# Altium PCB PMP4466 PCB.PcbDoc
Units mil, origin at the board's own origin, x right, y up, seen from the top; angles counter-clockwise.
Board outline 1720 x 1390 mil, 2 copper layers (Top Layer, Bottom Layer), stack 62 mil thick; 65 components, 38 nets, 155 pads, 8 vias.
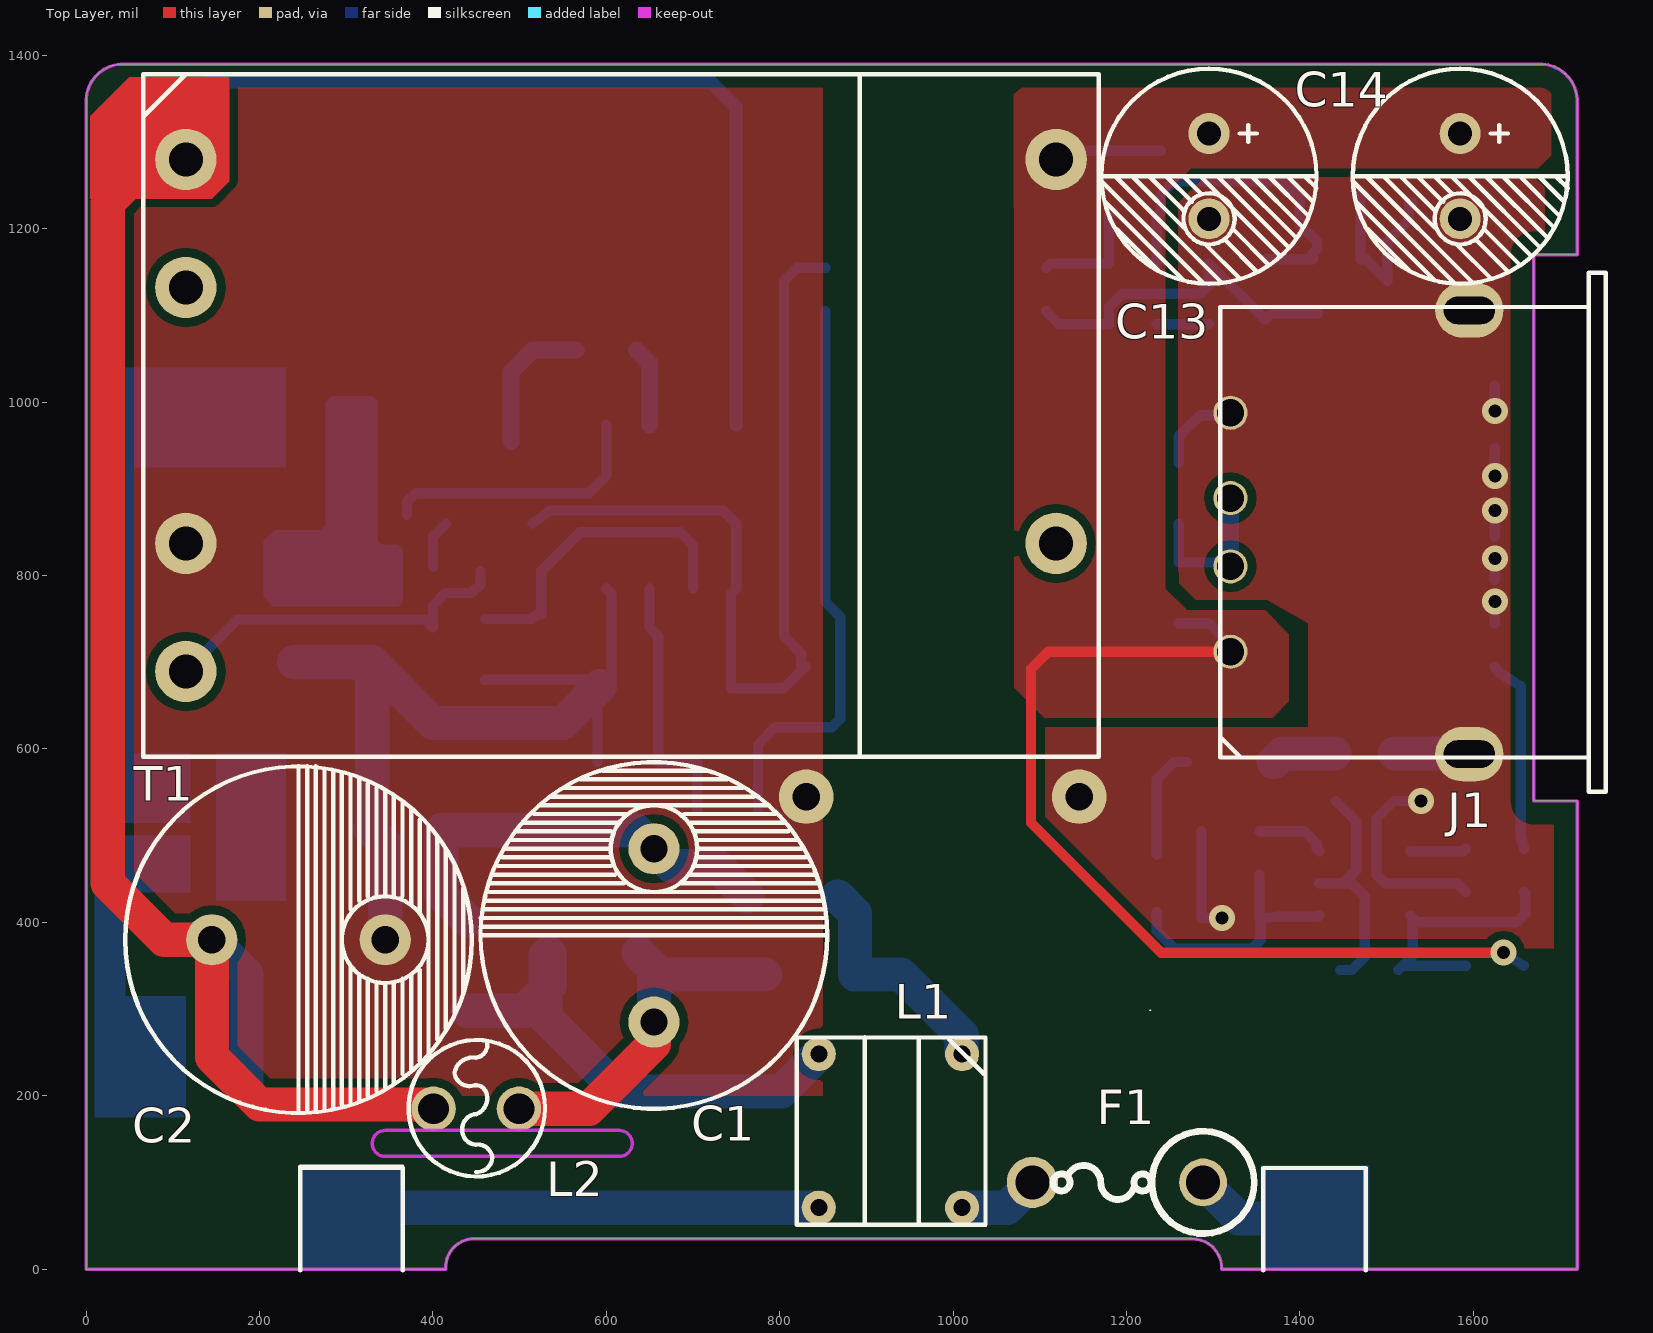
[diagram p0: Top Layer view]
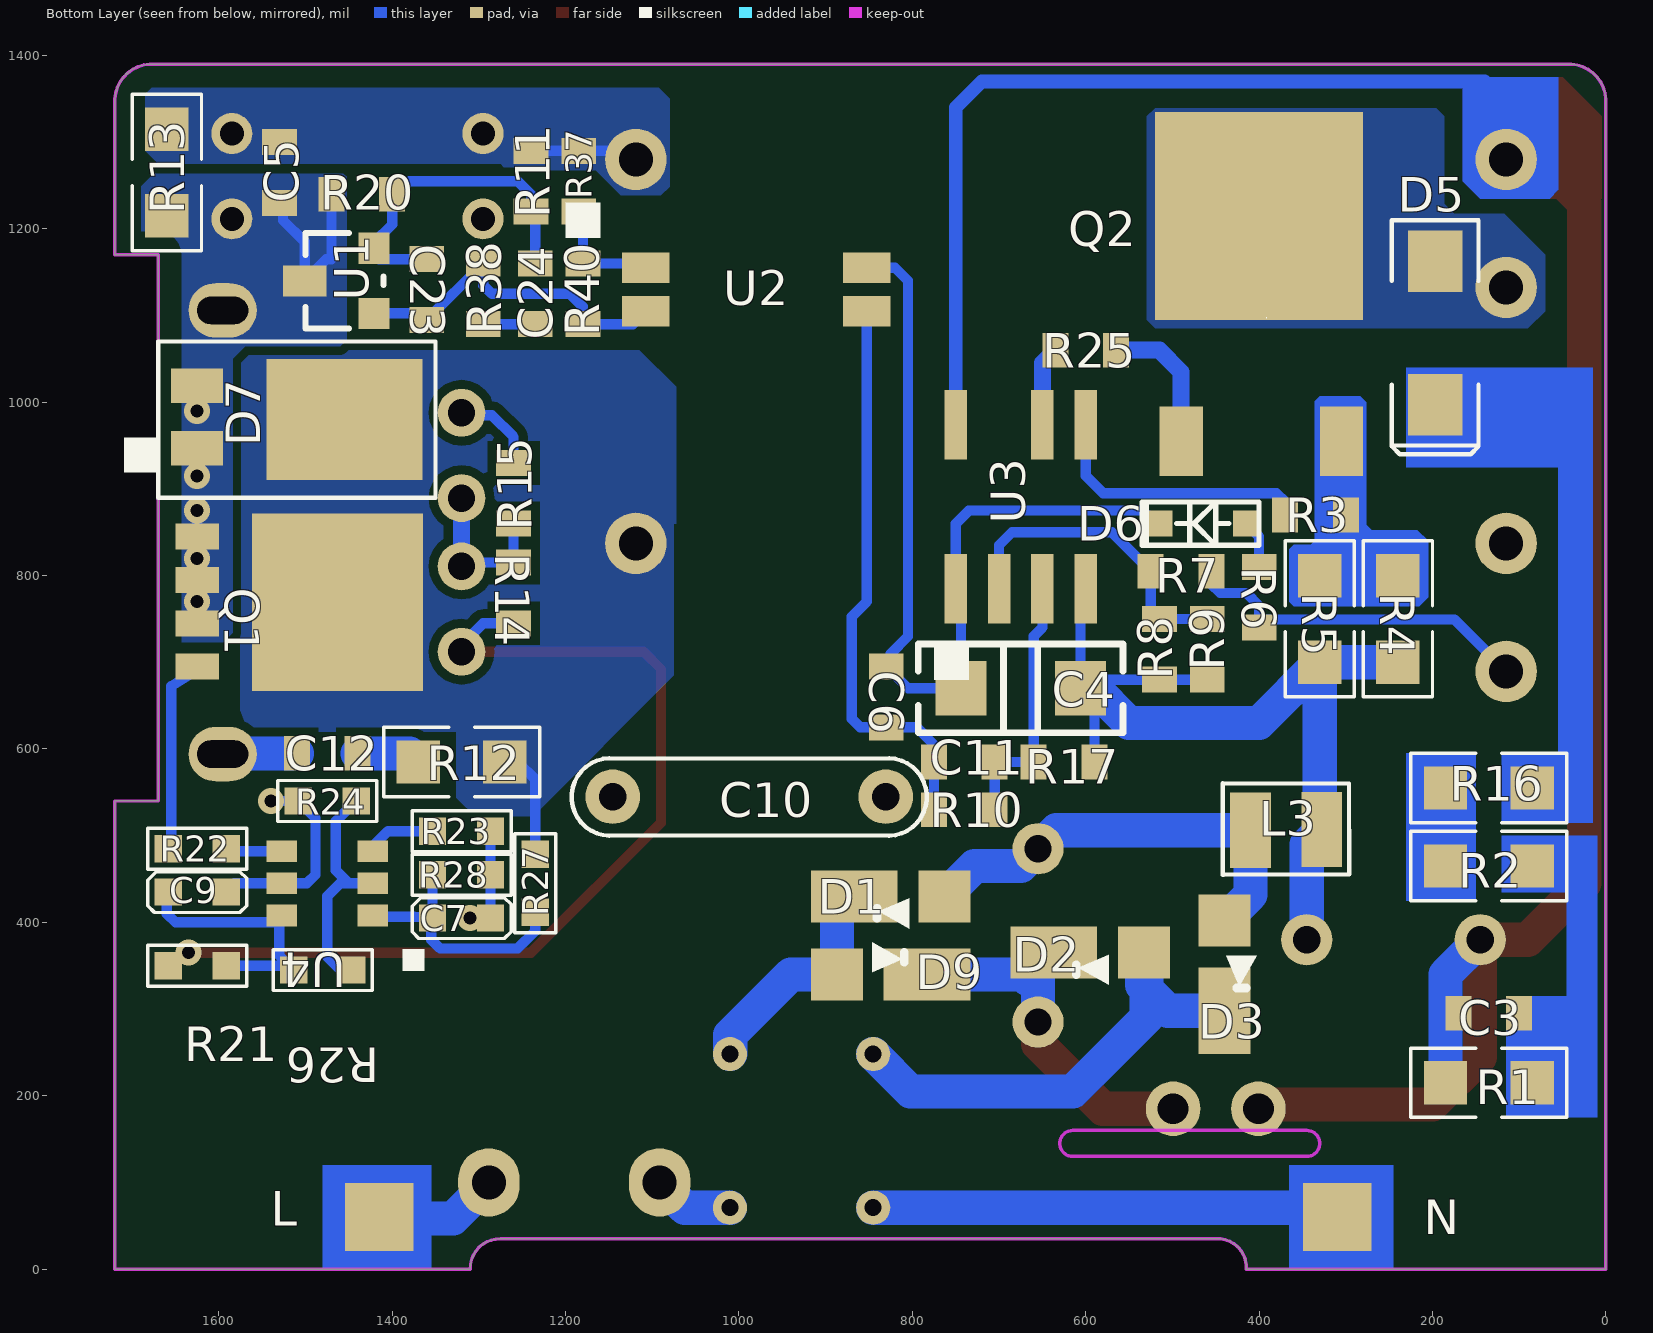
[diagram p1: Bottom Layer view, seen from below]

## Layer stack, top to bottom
Top Solder: solder mask 0.4, Solder Resist, Dk 3.5
Top Layer: signal copper 1.4
Dielectric1: core 59.2, FR-4, Dk 4.8
Bottom Layer: signal copper 1.4
Bottom Solder: solder mask 0.4, Solder Resist, Dk 3.5

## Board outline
0,0 0,1350 0,1349.95 cw(c42.5,1347.5) 39.98,1390 40,1390 1680,1390 1679.95,1390 cw(c1677.5,1347.5) 1720,1350.02 1720,1350 1720,1170 1670,1170 1670,540 1720,540 1720,0 1310,0 ccw(c1275.83,0.83) 1275,35 450,35 ccw(c447.5,2.5) 415,0

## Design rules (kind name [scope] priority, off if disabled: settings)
AcuteAngle [All] p1: minimum=4.50000000000000E+0001 checktracksonly=FALSE
AssemblyTestPointUsage [All] p1: valid=2
Clearance Clearance_BoardEdge_MountingHoles [OnCopper and InComponentClass('Mounting Holes') vs IsKeepOut] p1: gap=40
Clearance Clearance_BoardEdge_Poly [OnCopper and InPoly vs IsKeepOut] p2: gap=25
Clearance Clearance_BoardEdge [OnCopper and Not InComponentClass('Logo') and not InComponentClass('FiducialMark') and not InRegion(1000,500,4000,800) and Not IsKeepout vs IsKeepOut] p3: gap=5
Clearance Clearance_Poly [InPolygon] p4: gap=6
Clearance [All] p5: gap=6
ComponentClearance ComponentClearance_Logo [All] p1: gap=10 collisioncheckmode=3 verticalgap=10 showdistances=TRUE
ComponentClearance ComponentClearance_ScrewToNut [(HasFootprint('NY PMS 440 0025 PH')) vs (HasFootprint('Keystone_1902C'))] p2: gap=5 collisioncheckmode=3 verticalgap=10 showdistances=FALSE
ComponentClearance ComponentClearance_MountingHoles [InComponentClass('Mounting Holes')] p3: gap=10 collisioncheckmode=3 verticalgap=100000 showdistances=FALSE
ComponentClearance ComponentClearance_SmallPassives [HasFootprint('0201*') or HasFootprint('0402*') or HasFootprint('0508') or HasFootprint('0603*') or HasFootprint('0612') or HasFootprint('0805*') or HasFootprint('0815*') or HasFootprint('0830*') or HasFootprint('1206*') or HasFootprint('1210*') or HasFootprint('1808*') or HasFootprint('1812*') or HasFootprint('1825*') or HasFootprint('2010*') or HasFootprint('2220*') or HasFootprint('2225*') or HasFootprint('2512*') or HasFootprint('2728*') or HasFootprint('3518*') vs HasFootprint('0201*') or HasFootprint('0402*') or HasFootprint('0508') or HasFootprint('0603*') or HasFootprint('0612') or HasFootprint('0805*') or HasFootprint('0815*') or HasFootprint('0830*') or HasFootprint('1206*') or HasFootprint('1210*') or HasFootprint('1808*') or HasFootprint('1812*') or HasFootprint('1825*') or HasFootprint('2010*') or HasFootprint('2220*') or HasFootprint('2225*') or HasFootprint('2512*') or HasFootprint('2728*') or HasFootprint('3518*')] p4: gap=10 collisioncheckmode=3 verticalgap=10 showdistances=FALSE
ComponentClearance ComponentClearance_THtoSMT [IsThruComponent vs IsSMTComponent] p5: gap=10 collisioncheckmode=3 verticalgap=100000 showdistances=FALSE
ComponentClearance ComponentClearance_THtoTH [IsThruComponent vs IsThruComponent] p6: gap=10 collisioncheckmode=3 verticalgap=100000 showdistances=FALSE
ComponentClearance [All] p7: gap=10 collisioncheckmode=3 verticalgap=10 showdistances=FALSE
DiffPairsRouting [All] p1: maxlimit=100 minlimit=10 mostfreqgap=10 toplayer_minwidth=15 toplayer_maxwidth=15 toplayer_prefwidth=15 bottomlayer_minwidth=15 bottomlayer_maxwidth=15 bottomlayer_prefwidth=15 maxuncoupledlength=1000
FabricationTestPointUsage TestPointUsage [All] p1: valid=2 allowmultiple=FALSE
FabricationTestpoint Testpoint [All] p1: side=3 testpointundercomponent=TRUE minsize=40 maxsize=100 preferedsize=60 minholesize=0 maxholesize=40 preferedholesize=32 testpointgrid=1 allowsidetop=TRUE allowsidebottom=TRUE usegrid=TRUE gridtolerance=0.01
FanoutControl Fanout_LCC [IsLCC] p1: bgadir=Out bgaviamode=Centered fanoutstyle=Auto fanoutdirection=Alternating viagrid=1 // Fanout_LCC (Default Rule)
FanoutControl Fanout_BGA [IsBGA] p2: bgadir=Out bgaviamode=Centered fanoutstyle=Auto fanoutdirection=Alternating viagrid=1 // Fanout_BGA (Default Rule)
FanoutControl Fanout_Default [All] p4: bgadir=Out bgaviamode=Centered fanoutstyle=Auto fanoutdirection=Alternating viagrid=1 // Fanout_Default (Default Rule)
FanoutControl Fanout_Small [(CompPinCount < 5)] p5: bgadir=Out bgaviamode=Centered fanoutstyle=Auto fanoutdirection=OutThenIn viagrid=1 // Fanout_Small (Default Rule)
HoleSize [All] p1: absolutevalues=TRUE maxlimit=251 minlimit=6 maxpercent=80.000 minpercent=20.000
MinimumAnnularRing [All] p1: minimumring=3
MinimumSolderMaskSliver MinimumSolderMaskSliver_Logo [InComponentClass('Logo') vs InComponentClass('Logo')] p1: minsoldermaskwidth=0.7
MinimumSolderMaskSliver [All] p2: minsoldermaskwidth=0
PlaneConnect [All] p1: planeconnectstyle=Direct reliefexpansion=10 reliefentries=4 reliefconductorwidth=10 reliefairgap=10
PolygonConnect [All] p1: connectstyle=Direct reliefconductorwidth=10 reliefentries=4 polygonreliefangle="90 Angle" airgapwidth=10
RoutingCorners [All] p1: cornerstyle=45-Degree minsetback=10 maxsetback=100
RoutingVias [All] p1: holewidth=16 width=34 viastyle="Through Hole" minholewidth=8 minwidth=16 maxholewidth=40 maxwidth=65
SMDToCorner [All] p1: distance=0
SilkToSilkClearance [All] p1: silktosilkclearance=0
SilkToSolderMaskClearance SilkscreenOverComponentPads [IsPad] p1: minsilkscreentomaskgap=0 clearancetoexposedcopper=TRUE
SolderMaskExpansion [All] p1: expansion=3
UnpouredPolygon [All] p1: allowunpoured=FALSE
Width [All] p1: maxlimit=100 minlimit=6 preferedwidth=10 checkconnectedcopper=TRUE
14 further rules are at their usual default settings.

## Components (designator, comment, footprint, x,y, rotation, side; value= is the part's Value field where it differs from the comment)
C1 "ECAP$5C$200$5C$400A" ECAP$5C$200$5C$400A 655,285 r90 top
C2 "ECAP$5C$200$5C$400A" ECAP$5C$200$5C$400A 145,380 r0 top
C3 "C603" C603 135,295 r0 bottom
C4 "C1206" C1206 675,670 r0 bottom
C5 "C603" C603 1530,1265 r90 bottom
C6 "C603" C603 830,660 r90 bottom
C7 "0603C(W)$2F$3" 0603C(W)$2F$3 1320,405 r0 bottom
C9 "0603C(W)$2F$3" 0603C(W)$2F$3 1625,435 r0 bottom
C10 "Y-CAP" Y-CAP 1185,545 r180 bottom
C11 "C603" C603 740,585 r180 bottom
C12 "C603" C603 1475,595 r180 bottom
C13 "ECAP$5C$2.5$5C$6.3" ECAP$5C$2.5$5C$6.3 1295.28,1309.96 r270 top
C14 "ECAP$5C$2.5$5C$6.3" ECAP$5C$2.5$5C$6.3 1585,1309.96 r270 top
C23 "C603" C603 1360,1130 r270 bottom
C24 "C603" C603 1235,1125 r270 bottom
D1 "POWERDI_123" POWERDI_123 825,430 r180 bottom
D2 "POWERDI_123" POWERDI_123 595,365 r180 bottom
D3 "POWERDI_123" POWERDI_123 440,340 r90 bottom
D5 "SMA" SMA 196.85,1080 r270 bottom
D6 "SOD323" SOD323 465,860 r0 bottom
D7 "POWER_DI" POWER_DI 1555,980 r270 bottom
D9 "POWERDI_123" POWERDI_123 825,340 r0 bottom
F1 "F-7.2X2.7-P5" F-7.2X2.7-P5 1190,100 r180 top
J1 "USB-BYDAAAAAA" USB-BYDAAAAAA 1320,850 r90 top
L "H1.0" H1.0 1415,60 r180 bottom
L1 "CMNEE8.3AA" CMNEE8.3AA 855,125 r0 top
L2 "L_0406A" L_0406A 450,185 r180 top
L3 "L-0805$2F$3" L-0805$2F$3 375,510 r180 bottom
N "H1.0" H1.0 310,60 r180 bottom
Q1 "QFN5X6MM" QFN5X6MM 1510,770 r270 bottom
Q2 "KTP" KTP 400,1125 r180 bottom
R1 "CAP$5C$0805$5C$B" CAP$5C$0805$5C$B 135,215 r180 bottom
R2 "CAP$5C$0805$5C$B" CAP$5C$0805$5C$B 135,465 r0 bottom
R3 "R603" R603 335,870 r0 bottom
R4 "CAP$5C$0805$5C$B" CAP$5C$0805$5C$B 240,750 r270 bottom
R5 "CAP$5C$0805$5C$B" CAP$5C$0805$5C$B 330,750 r270 bottom
R6 "R603" R603 400,775 r90 bottom
R7 "R603" R603 490,805 r0 bottom
R8 "R603" R603 515,715 r90 bottom
R9 "R603" R603 460,715 r90 bottom
R10 "R603" R603 740,530 r180 bottom
R11 "R603" R603 1240,1255 r270 bottom
R12 "CAP$5C$0805$5C$B" CAP$5C$0805$5C$B 1320,585 r0 bottom
R13 "CAP$5C$0805$5C$B" CAP$5C$0805$5C$B 1660,1265 r90 bottom
R14 "R603" R603 1260,780 r270 bottom
R15 "R603" R603 1260,895 r270 bottom
R16 "CAP$5C$0805$5C$B" CAP$5C$0805$5C$B 135,555 r180 bottom
R17 "R603" R603 625,585 r0 bottom
R20 "R603" R603 1435,1240 r0 bottom
R21 "0603(W)" 0603(W) 1625,350 r0 bottom
R22 "0603(W)" 0603(W) 1625,485 r0 bottom
R23 "0603(W)" 0603(W) 1320,505 r0 bottom
R24 "0603(W)" 0603(W) 1475,540 r180 bottom
R25 "R603" R603 600,1060 r0 bottom
R26 "0603(W)" 0603(W) 1480,345 r0 bottom
R27 "0603(W)" 0603(W) 1235,445 r90 bottom
R28 "0603(W)" 0603(W) 1320,455 r0 bottom
R37 "R603" R603 1185,1255 r270 bottom
R38 "R603" R603 1295,1125 r90 bottom
R40 "R603" R603 1180,1125 r270 bottom
T1 "EFD20-2AAA" EFD20-2AAA 115,1280 r0 top
U1 "TL431AIDBZ" TL431AIDBZ 1460,1140 r90 bottom
U2 "MF4" MF4 980,1130 r180 bottom
U3 "SO8[7P]" SO8[7P] 675,880 r90 bottom
U4 "SOT23-6P" SOT23-6P 1475,445 r0 bottom

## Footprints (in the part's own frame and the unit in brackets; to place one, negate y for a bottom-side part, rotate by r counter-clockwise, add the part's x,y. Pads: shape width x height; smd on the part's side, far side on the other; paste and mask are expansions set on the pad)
0603(W) [mm]
  rect 0.8x0.8 smd mask+0.03: 1(-0.85,0) 2(0.85,0)
  silkscreen extent -1.45,-0.6 1.45,0.6
0603C(W)$2F$3 [mm]
  rect 0.8x0.8 smd mask+0.03: 1(-0.85,0) 2(0.85,0)
  silkscreen extent -1.45,-0.6 1.45,0.6
C603 [mil]
  rect 30x40 smd mask+2: 1(-35,0) 2(35,0)
C1206 [mm]
  rect 1.5x1.6 smd: 1(-1.75,0) 2(1.75,0)
  silkscreen extent -3,-1.3 3,1.3
CAP$5C$0805$5C$B [mil]
  rect 50x50 smd: 1(-50,0) 2(50,0)
  silkscreen extent -90,-40 90,40
CMNEE8.3AA [mm]
  round 1 hole 0.5: 1(3.95,3.125) 2(3.95,-1.375) 3(-0.25,3.125) 4(-0.25,-1.375)
  silkscreen extent -0.9,-1.88 4.63,3.62
ECAP$5C$2.5$5C$6.3 [mm]
  round 1.2 / inner round 1.8 / far side round 1.2 hole 0.7: 1(0,0) 2(2.5,0)
  silkscreen extent -1.9,-3.15 4.4,3.15
ECAP$5C$200$5C$400A [mm]
  round 1.5 hole 0.8: 1(0,0) 2(5.08,0)
  silkscreen extent -2.54,-5.08 7.62,5.08
EFD20-2AAA [mm]
  round 1.8 hole 1: 1(0,0) 2(0,-3.75) 4(0,-11.25) 5(0,-15) 7(25.5,-11.25) 10(25.5,0)
  silkscreen extent -1.25,-17.5 26.75,2.5
F-7.2X2.7-P5 [mm]
  round 1.4 / inner oval 1.8x2 / far side oval 1.8x2 hole 1 mask+0.03: 1(-2.5,0)
  round 1.5 / inner oval 1.8x2 / far side oval 1.8x2 hole 1 mask+0.03: 2(2.5,0)
  silkscreen extent -4,-1.5 1.9,1.5
H1.0 [mm]
  rect 2x2 smd: 1(0,0)
KTP [mil]
  rect 50x80 smd: 1(-90,-170) 2(95,-170)
  rect 240x240 smd: 3(0,90)
  silkscreen extent 9,-28 9,-27
L-0805$2F$3 [mm]
  rect 1.2x2.2 smd: 1(1.2,-0.075) 2(-0.89,-0.096)
  silkscreen extent -1.7,-1.41 2,1.28
L_0406A [mm]
  round 1.3 / inner round 1.6 / far side round 1.6 hole 0.9: 1(-1.25,0) 2(1.25,0)
  silkscreen extent -2.02,-2.01 1.98,1.98
MF4 [mil]
  rect 55x35 smd: 1(-127.5,25) 2(-127.5,-25) 3(127.5,-25) 4(127.5,25)
  silkscreen extent -220,60 -180,100
POWER_DI [mil]
  rect 40x60 smd: 1(-39,-70) 3(33,-70)
  rect 140x180 smd: 2(0,100)
  silkscreen extent -90,-115 90,205
POWERDI_123 [mil]
  rect 100x60 smd: 1(-42,0)
  rect 60x60 smd: 2(62,0)
  silkscreen extent -16,-37 21,-2
QFN5X6MM [mil]
  rect 30x50 smd mask+0.1: 1(-75,-115) 2(-25,-115) 3(25,-115) 4(75,-115)
  rect 204.72x196.85 smd: 5(0.79,46.85)
  silkscreen extent -189,-199 -149,-159
R603 [mil]
  rect 30x40 smd: 1(-35,0) 2(35,0)
SMA [mm]
  rect 1.8x1.6 smd: 1(2.1,0) 2(-2.1,0)
  silkscreen extent -3.3,-1.27 3.56,1.27
SO8[7P] [mil]
  rect 80x26 smd: 1(-95,75) 2(-95,25) 3(-95,-25) 4(-95,-75) 5(94,-75) 6(94,-25) 8(94,75)
  silkscreen extent -200,60 -160,100
SOD323 [mil]
  rect 30x30 smd: 1(50,0) 2(-50,0)
  silkscreen extent -65,-25 70,25
SOT23-6P [mil]
  rect 35x25 smd: 1(-52.5,37) 2(-52.5,0) 3(-52.5,-37) 4(52.5,-37) 5(52.5,0) 6(52.5,37)
  silkscreen extent -112,76 -87,101
TL431AIDBZ [mil]
  rect 36x36 smd: 1(-37.5,-39) 2(37.5,-39)
  rect 36x50 smd: 3(0,41)
  silkscreen extent -55,-50 55,40
USB-BYDAAAAAA [mm]
  round 1 / inner round 1.4 / far side round 1.4 hole 0.8: 1(-3.5,0) 2(-1,0) 3(1,0) 4(3.5,0)
  oval 1.6x2 hole 0.8 slot 1.5 at 90 deg: 5(-6.5,-7) 6(6.5,-7)
  silkscreen extent -7.6,-11 7.6,0.3
Y-CAP [mm]
  round 1.6 hole 0.8: 1(1,0) 2(9,0)
  silkscreen extent -0.2,-1.15 10.2,1.13

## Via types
v1: diameter 30, hole 15, Top Layer to Bottom Layer, 8 vias

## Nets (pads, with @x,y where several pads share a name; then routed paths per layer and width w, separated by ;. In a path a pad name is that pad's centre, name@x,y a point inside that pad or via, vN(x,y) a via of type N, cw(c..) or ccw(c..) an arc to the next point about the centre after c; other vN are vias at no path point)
$$$1: C12.2 R12.2 | length 74.1
  Bottom Layer w39.37: R12.2 1380,595 C12.2
$$$980: C3.1 R1.2 R2.1
$$$2093: R37.2 R40.1 U2.1 | length 136.6
  Bottom Layer w11.81: U2.1 1112.5,1160 R40.1 1180,1215 R37.2
$$$2515: Q2.2 R3.1 R4.1 R5.1
$$$4302: R3.2 U3.5 | length 316.4
  Bottom Layer w11.81: R3.2 370,885 380,895 580,895 600,915 U3.5
$$$4615: R25.2 U3.6 | length 92.2
  Bottom Layer w19.68: R25.2 650,1045 U3.6
$$$5424: D5.1 R16.2
$$$6648: C11.2 R10.2 R17.2 U3.3 | length 304.1
  Bottom Layer w11.81: U3.3 650,740 660,730 R17.2 C11.2 R10.2
$$$6732: C6.1 C11.1 R10.1 U2.3 | length 659.7
  Bottom Layer w11.81: R10.1 C11.1 775,605 795,625 C6.1 860,625 870,635 870,752.5 852.5,770 U2.3
$$$7639: C5.2 C13.1 C14.1 J1.1 R11.1 R13.2 R14.2 R21.2 R37.1 T1.10 | length 1253.8
  Top Layer w11.81: J1.1 1110,712.2 1090,692.2 1090,515 1240,365 v1(1635,365)
  Bottom Layer w11.81: T1.10 1128.94,1290 R37.1 R11.1 ; R14.2 1295,745 1320,720 J1.1 ; v1(1635,365) R21.2
$$$11187: Q2.1 R25.1 | length 165.4
  Bottom Layer w19.68: Q2.1 490,1035 515,1060 R25.1
$$$14440: C23.2 R38.2 R40.2 U1.1 U2.2 | length 405.1
  Bottom Layer w11.81: U2.2 1122.5,1090 R40.2 1180,1110 1195,1125 1285,1125 1295,1135 R38.2 C23.2 1367.5,1102.5 U1.1
$$$15027: C2.1 C3.2 L2.2 R1.1 T1.1 U3.8 | length 2728.6
  Top Layer w39.37: C2.1 145,245 200,190 395.79,190 L2.2
  Top Layer w40: T1.1 75,1280 25,1230 25,445 90,380 C2.1
  Bottom Layer w15.75: T1.1 115,1345 140,1370 720,1370 750,1340 U3.8
  Bottom Layer w39.37: C2.1 185,340 185,295 R1.1
$$$15511: C1.1 D2.1 D9.1 L2.1 | length 434.4
  Top Layer w39.37: L2.1 580,185 655,260 C1.1
  Bottom Layer w39.37: D2.1 D2.1@655,347 ; C1.1 D2.1@655,347 ; D9.1 672,340 667,335 D2.1@655,347
$$$15883: F1.2 L1.2 | length 93.1
  Bottom Layer w39.37: L1.2 1062.44,70.87 F1.2
$$$15885: L1.4 N.1 | length 539.7
  Bottom Layer w39.37: N.1 320.87,70.87 L1.4
$$$15918: C9.2 R21.1 R26.2 U4.6 | length 305.9
  Bottom Layer w11.81: R26.2 R26.2@1518.46,350 ; U4.6 U4.6@1530.25,405.25 ; R21.1 R26.2@1518.46,350 ; C9.2 1660,433.46 1660,410 1650,400 1535.5,400 U4.6@1530.25,405.25 ; R26.2@1518.46,350 1530.25,361.79 U4.6@1530.25,405.25
$$$15978: R22.1 U4.4 | length 65.3
  Bottom Layer w11.81: U4.4 1588.54,482 R22.1
$$$15988: D1.1 D9.2 L1.1 | length 272.5
  Bottom Layer w39.37: D1.1 887,410 D9.2 940,340 1010,270 1010,248.54 L1.1
$$$15990: D2.2 D3.1 L1.3 | length 589.7
  Bottom Layer w39.37: D3.1 505,298 530,323 ; L1.3 802.13,205 615,205 530,290 530,323 ; 530,323 535,328 535,363 D2.2 530,362 530,323
$$$16008: R23.2 U4.3 | length 81.8
  Bottom Layer w11.81: R23.2 1405,505 1419.5,490.5 1419.5,485 U4.3
$$$16010: C1.2 D1.2 D3.2 L3.2 | length 501.2
  Bottom Layer w39.37: L3.2 410,432 D3.2 ; L3.2 633.78,506.22 C1.2 675,465 728,465 D1.2
$$$16065: R24.2 R26.1 U4.2 | length 274.3
  Bottom Layer w11.81: U4.2 1450,445 ; R24.2 1465,516.54 1465,460 1450,445 ; R26.1 1460,345 1475,360 1475,430 1460,445 1450,445
$$$16085: C7.2 R27.1 R28.2 U4.1 | length 298.8
  Bottom Layer w11.81: R27.1 1235,390 1255,370 1345,370 1354.99,379.99 1354.99,405 C7.2@1354.99,405.11 ; R28.2 1353.46,435 C7.2 C7.2@1354.99,405.11 ; U4.1 1421.04,406.54 1375,406.54 C7.2@1354.99,405.11
$$$18434: D5.2 Q2.3 T1.2
$$$19469: D7.2 Q1.5 R12.1 R27.2 T1.7 | length 129.8
  Bottom Layer w11.81: R27.2 1235,565 1255,585 R12.1
$$$20004: R7.2 R8.2 R9.2 U3.2 | length 366.9
  Bottom Layer w11.81: R9.2 R8.2 520,755 525,755 R7.2 570,850 685,850 700,835 U3.2
$$$21110: C4.2 C6.2 D6.1 U2.4 U3.1 | length 1047.2
  Bottom Layer w11.81: D6.1 535,875 735,875 750,860 U3.1 743.9,778.9 C4.2 805,670 C6.2@825,690 ; C6.2 C6.2@825,690 ; U2.4 820,1155 805,1140 805,730 825,710 825,695 C6.2@825,690
$$$24763: R2.2 R16.1
$$$26288: J1.2 J1.3 R14.1 R15.2 | length 183.7
  Bottom Layer w11.81: R15.2 R14.1 J1.2@1320,815
  Bottom Layer w20: J1.2 1320,815 J1.3
$$$27032: C24.2 R38.1 | length 60
  Bottom Layer w11.81: C24.2 R38.1
$$$29416: Q1.4 R22.2 | length 226.1
  Bottom Layer w11.81: Q1.4 1627.48,690.05 1655,672.52 1655,498.46 R22.2
$$$30096: F1.1 L.1 | length 144.4
  Bottom Layer w39.37: F1.1 1330,58.43 1413.43,58.43 L.1
$$$30409: R6.1 R7.1 T1.5 | length 419.1
  Bottom Layer w11.81: T1.5 175,749.45 390.55,749.45 R6.1 400,765 415,780 445,780 455,790 R7.1
$$$31676: C23.1 C24.1 R11.2 R20.1 U1.2 | length 397.8
  Bottom Layer w11.81: C24.1 1235,1215 R11.2 1240,1240 1255,1255 1380,1255 1397.5,1237.5 R20.1@1400,1235 ; C23.1 1415,1165 1415,1171.5 U1.2 1420,1178.5 1420,1185 1400,1205 R20.1@1400,1235 ; R20.1 R20.1@1400,1235
GND: C5.1 C7.1 C9.1 C10.1 C12.1 C13.2 C14.2 D7.1 D7.3 J1.4 J1.5 J1.6 Q1.1 Q1.2 Q1.3 R13.1 R15.1 R20.2 R23.1 R24.1 R28.1 U1.3 U4.5 | length 913.8
  Top Layer w11.81: v1(1625,915) v1@1625,920
  Bottom Layer w11.81: R15.1 1260,960 1285,985 1317.2,985 J1.4 ; R23.1 R28.1 C7.1 v1(1310,405) ; R20.2 1470,1165 1476,1165 U1.3 1501,1185 1526,1210 1526,1230 C5.1 ; v1(1540,540) R24.1 1488.46,520 1488.46,455 1498.46,445 U4.5 1581.54,445 C9.1 ; Q1.3 v1(1625,770) ; Q1.2 v1(1625,820) ; Q1.1 v1(1625,875) ; v1(1625,915) D7.3 ; v1(1625,990) D7.1
  Bottom Layer w39.37: C12.1 1594.69,595 J1.5
NET00062: D6.2 R6.2 | length 56.2
  Bottom Layer w11.81: R6.2 400,845 D6.2
PWRGND: C2.2 C4.1 C10.2 L3.1 R4.2 R5.2 R8.1 R9.1 R17.1 T1.4 U3.4 | length 1084
  Bottom Layer w11.81: R9.1 R8.1 585,680 592.5,672.5 C4.1@600.55,664.45 ; R17.1 590,655 591.1,655 C4.1@600.55,664.45 ; U3.4 606.1,778.9 C4.1 C4.1@600.55,664.45
  Bottom Layer w39.37: R4.2 R5.2 ; C2.2 345,489.8 L3.1 330,509.29 R5.2 ; C4.1@592.5,672.5 550,630 400,630 R5.2

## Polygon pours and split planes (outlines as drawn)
GND on Bottom Layer "Bottom-GND" (solid, remove dead copper, pour order 2): 1452.28,1105 1452.5,1117.5 1452.5,1260 1456.25,1263.75 1675,1263.75 1689.38,1249.38 1689.38,1185 1682.19,1177.81 1671.41,1177.81 1665,1171.41 1665,730 1658.2,723.2 1595,723.2 1584.1,734.1 1584.1,1050 1569.55,1064.55 1460,1064.55 1452.28,1072.28
$$$18434 on Bottom Layer "Bottom-$$$18434" (solid, remove dead copper, pour order 4): 70,1105.16 70,1170 117.5,1217.5 175,1217.5 186.25,1228.75 186.25,1330 195.63,1339.38 520,1339.38 529.69,1329.69 529.69,1095 519.84,1085.16 90,1085.16
$$$7639 on Bottom Layer "Bottom-$$$7639" (solid, remove dead copper, pour order 10): 1080,1248.75 1080,1350 1105,1375 1665,1375 1685,1355 1685,1290 1670,1275 1275,1275 1267.5,1267.5 1165,1267.5 1136.25,1238.75 1090,1238.75
$$$19469 on Bottom Layer "Bottom-$$$19469" (solid, remove dead copper, pour order 12): 1075,860 1075,685 1237.5,522.5 1305,522.5 1326.25,543.75 1326.25,620 1565,620 1575.31,644.69 1575.31,1050 1565.16,1060.16 1115,1060.16 1072.42,1017.58 1072.42,860
$$$7639 on Top Layer "Top-$$$7639" (solid, remove dead copper, pour order 6): 1070,1225 1070,1355 1100,1380 1670,1380 1690,1360 1690,1285 1675,1270 1275,1270 1245,1240 1245,785 1270,760 1360,760 1387.5,732.5 1387.5,655 1368.75,636.25 1105,636.25 1070.62,670.62 1070.62,1225
PWRGND on Top Layer "Top-PWRGND" (solid, remove dead copper, pour order 8): 45,200 850,200 850,1370 45,1370
GND on Top Layer "Top-GND" (solid, remove dead copper, pour order 14): 1260,805 1260,1230 1290,1260 1670,1260 1682.5,1247.5 1682.5,1195 1655,1171.25 1655,540 1674.38,524.38 1700,524.38 1709.69,514.69 1709.69,370 1250,370 1105,515 1105,625 1410,625 1410,745 1361.91,771.91 1280,771.91 1260.96,790.96 1260.96,805

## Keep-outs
Keep-Out Layer:
  lines w3.94: 0,1349.95 cw(c42.5,1347.5) 39.98,1390 1680,1390 ; 0,1350 0,0 415,0 cw(c447.5,2.5) 450,35 1275,35 cw(c1275.83,0.83) 1310,0 1720,0 1720,540 1670,540 1670,1170 1720,1170 1720,1350 ccw(c1677.5,1347.5) 1679.95,1390 ; 345,130 cw(c345,145) 345,160 615,160 cw(c615,145) 615,130 345,130
  text ".Layer_Name" at 577,-858.49 h60

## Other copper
Top Layer:
  region net $$$15027: 50,1375 165,1375 165,1255 145,1235 5,1235 5,1330 50,1375
  text ".Layer_Name" at 577,-858.49 h60
Bottom Layer:
  region net $$$980: 10,175 10,500 120,500 120,435 45,435 45,315 115,315 115,175 10,175
  region net $$$15027: 65,1235 145,1235 165,1255 165,1375 55,1375 55,1245 65,1235
  region net $$$24763: 150,425 150,595 230,595 230,425 150,425
  region: 245,120 365,120 365,0 245,0
  region net $$$2515: 205,774.88 205,840 217.5,852.5 270,852.5 276.25,858.75 276.25,1000 283.13,1006.88 330,1006.88 335.94,1000.94 335.94,840 340.47,835.47 360,835.47 365.23,830.23 365.23,770 360.12,764.88 215,764.88 205,774.88
  region: 1355,120 1480,120 1480,0 1355,0
  region net $$$5424: 15,515 120,515 120,595 55,595 55,925 230,925 230,1040 15,1040 15,515
  text ".Layer_Name" at 577,-858.49 h60

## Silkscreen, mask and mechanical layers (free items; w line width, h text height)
Top Overlay:
  lines w1.97: 1226.96,298.46 1227.94,298.46
  lines w5: 246.89,0 246.89,118.11 365,118.11 365,0 ; 247.09,-1.52 247.09,116.59 365.2,116.59 365.2,-1.52 ; 1357.97,-1.52 1357.97,116.59 1476.08,116.59 1476.08,-1.52
  text ".Layer_Name" at 577,-858.49 h60
Bottom Overlay:
  text ".Layer_Name" at 577,-858.49 h60
Top Paste:
  text ".Layer_Name" at 577,-858.49 h60
Bottom Paste:
  lines w23.62: 262.94,9.77 262.94,105.77 ; 304.94,12.77 304.94,108.77 ; 349.94,10.77 349.94,106.77 ; 1371,11 1371,107 ; 1415,11 1415,107 ; 1460,10 1460,106
  text ".Layer_Name" at 577,-858.49 h60
Top Solder:
  text ".Layer_Name" at 577,-858.49 h60
  text ".Layer_Name" at 577,-858.49 h60
Bottom Solder:
  lines w23.62: 263.14,8.25 263.14,104.25 ; 305.14,11.25 305.14,107.25 ; 350.14,9.25 350.14,105.25 ; 1372.14,9.25 1372.14,105.25 ; 1416.14,9.25 1416.14,105.25 ; 1461.14,8.25 1461.14,104.25
  text ".Layer_Name" at 577,-858.49 h60
Drill Guide:
  text ".Layer_Name" at 577,-858.49 h60
M1 Board Outline:
  text ".Layer_Name" at 577,-858.49 h60
M2 Board Dimensions:
  rectangle: 125,-400 500,-275
  rectangle: 0,-275 125,-150
  lines w7: 0,-275 1000,-275 ; 0,-150 0,-400 1000,-400 1000,-150 ; 125,-400 125,-150 ; 250,-400 250,-150 ; 500,-400 500,-150 ; 750,-400 750,-150
  text ".Layer_Name" at 577,-858.49 h60
M3 3D STEP Top:
  text ".Layer_Name" at 577,-858.49 h60
M4 3D STEP Bottom:
  text ".Layer_Name" at 577,-858.49 h60
M5 Assembly Top:
  lines w10: -292,-930.17 6308,-930.17 ; -292,-726.83 6310,-726.83 ; -292,-523.5 -292,-1133.5 3713,-1133.5 6310,-1133.5 6310,-523.5 -291.5,-523.5 -291.5,-1133.5 1284,-1133.5 ; 2173,-1133.5 2173,-523.5 ; 3440,-726.83 3440,-523.5 ; 4280,-726.83 4280,-523.5 ; 4902,-1140 4902,-937.17
  text "COMPONENTS MARKED 'DNP' SHOULD NOT BE POPULATED." at 1153.5,-318.5 h60
  text "ASSEMBLY VARIANT:" at 1153,-434 h60
  text ".VariantName" at 2189,-434 h60
  text "PCB VIEWED FROM TOP SIDE" at -228.5,-655.67 h60
  text "BOARD #:" at 2248,-655.67 h60
  text ".PRJ_Number" at 2793.5,-655.67 h60
  text "REV:" at 3638,-655.67 h60
  text ".PCB_Rev" at 3929.5,-655.67 h60
  text "SVN REV:" at 4476,-655.67 h60
  text ".VersionControl_RevNumber" at 4982,-655.67 h60
  text "TID #:" at 2248,-859 h60
  text ".TID" at 2793.5,-859 h60
  text "PLOT NAME =" at -228.5,-1064.34 h60
  text ".plot_File_Name" at 577,-1064.34 h60
  text "GENERATED    :" at 2250,-1064.34 h60
  text ".Print_Date" at 3119.5,-1064.34 h60
  text ".Print_Time" at 3848.5,-1064.34 h60
  text "TEXAS INSTRUMENTS" at 5113,-1064.34 h60
M6 Assembly Bottom:
  lines w10: -292.5,-727.33 6309.5,-727.33 ; -290.5,-930.67 6309.5,-930.67 ; 1115.5,-1140.5 1115.5,-937.67 ; 1737.5,-727.33 1737.5,-524 ; 2577.5,-727.33 2577.5,-524 ; 3844.5,-1134 3844.5,-524 ; 4733.5,-1134 6309,-1134 6309,-524 -292.5,-524 -292.5,-1134 2304.5,-1134 6309.5,-1134 6309.5,-524
  text "COMPONENTS MARKED 'DNP' SHOULD NOT BE POPULATED." at 6102,-318 h60
  text ".VariantName" at 5058,-434 h60
  text "ASSEMBLY VARIANT:" at 6097,-434 h60
  text ".VersionControl_RevNumber" at 1035.5,-656.17 h60
  text "SVN REV:" at 1541.5,-656.17 h60
  text ".PCB_Rev" at 2088,-656.17 h60
  text "REV:" at 2379.5,-656.17 h60
  text ".PRJ_Number" at 3224,-656.17 h60
  text "BOARD #:" at 3769.5,-656.17 h60
  text "PCB VIEWED FROM BOTTOM SIDE" at 6246,-656.17 h60
  text ".TID" at 3224,-859.5 h60
  text "TID #:" at 3769.5,-859.5 h60
  text "TEXAS INSTRUMENTS" at 904.5,-1064.84 h60
  text ".Print_Time" at 2169,-1064.84 h60
  text ".Print_Date" at 2898,-1064.84 h60
  text "GENERATED    :" at 3767.5,-1064.84 h60
  text ".plot_File_Name" at 5440.5,-1064.84 h60
  text "PLOT NAME =" at 6246,-1064.84 h60
M9 Title Sheet:
  drawing of 57 lines, arcs and shapes, not listed
  text "1" at 739.84,8036.5 h70
  text "2" at 3235.5,8036.5 h70
  text "3" at 5724.84,8036.5 h70
  text "4" at 8231.51,8036.5 h70
  text "5" at 10730.5,8036.5 h70
  text "6" at 13235.5,8036.5 h70
  text "A" at -416.5,6893.5 h70
  text "A" at 14383.5,6893.5 h70
  text "B" at -416.5,4513.5 h70
  text "B" at 14383.5,4513.5 h70
  text "C" at -416.5,2138.5 h70
  text "C" at 14383.5,2138.5 h70
  text "PROJECT TITLE:" at 11343.5,277.5 h45
  text ".PRJ_Title" at 11393.5,144.17 h70
  text "DESIGNED FOR:" at 11343.5,-23.5 h45
  text ".PRJ_Customer" at 11393.5,-163.5 h70
  text "D" at -416.5,-231.5 h70
  text "D" at 14383.5,-231.5 h70
  text "FILE NAME:" at 11343.5,-323.5 h45
  text ".PCB_File_Name_No_Path" at 11393.5,-443.5 h70
  text "Texas Instruments (TI) and/or its licensors do not warrant the accuracy or completeness of this specification" at 6374,-605.34 h45
  text "ENGINEER:" at 11343.5,-613.5 h45
  text "LAYOUT BY:" at 12848.5,-613.5 h45
  text "or any information contained therein. TI and/or its licensors do not warrant that this design will meet" at 6329.01,-718 h45
  text ".PRJ_Engineer" at 11393.5,-768.49 h70
  text ".PCB_Layout" at 12899,-768.49 h70
  text "the specifications, will be suitable for your application or fit for any particular purpose, or will operate in" at 6329.01,-830.67 h45
  text ".Layer_Name" at 577,-858.49 h60
  text "ALTIUM DESIGNER VERSION:" at 12848.5,-923.5 h45
  text "an implementation. TI and/or its licensors do not warrant that the design is production worthy. You should" at 6329.01,-943.33 h45
  text "completely validate and test your design implementation to confirm the system functionality for your application." at 6374,-1056 h45
  text ".print_Scale" at 11393.5,-1056.83 h70
  text ".Application_BuildNumber" at 12899,-1056.83 h70
  text "1" at 739.84,-1263.5 h70
  text "2" at 3235.5,-1263.5 h70
  text "3" at 5724.84,-1263.5 h70
  text "4" at 8231.51,-1263.5 h70
  text "5" at 10730.5,-1263.5 h70
  text "6" at 13235.5,-1263.5 h70
M10 Fab Notes:
  drawing of 173 lines, arcs and shapes, not listed
  text "DESIGN INFORMATION" at 12377.02,6201 h60
  text "MIN. TRACK WIDTH:" at 11732.46,6021 h60
  text "8" at 12828.7,6021 h60
  text "MIL" at 12983.46,6021 h60
  text "MIN. CLEARANCE:" at 11732.46,5889 h60
  text "0.2" at 12768.7,5889 h60
  text "mm" at 12983.46,5889 h60
  text "MIN. VIA PAD SIZE:" at 11732.46,5757 h60
  text "24" at 12798.71,5757 h60
  text "MIL" at 12983.46,5757 h60
  text "0.05mm (2MIL)" at 12427.46,5615.29 h60
  text "MINIMUM ANNULAR RING" at 11403.23,5611 h60
  text "EXTERNAL" at 13135.46,5611 h60
  text "PER" at 11603.23,5493 h60
  text "IPC-D-275 CLASS 2 LEVEL C" at 11823.23,5493 h60
  text "MIL, HOLES" at 13311.46,5380.71 h60
  text "+/-" at 12919,5380 h60
  text "+/-" at 13773,5380 h60
  text "REGISTRATION TOLERANCES:" at 11403.23,5375 h60
  text "METAL" at 12603,5375 h60
  text "5" at 13179.2,5375 h60
  text "3" at 14012.2,5375 h60
  text "MIL" at 14128.46,5375 h60
  text "+/-" at 13773,5262 h60
  text "HOLE SIZE TOLERANCE (UNLESS OTHERWISE SPECIFIED):" at 11403.23,5257 h60
  text "3" at 14012.2,5257 h60
  text "MIL" at 14128.46,5257 h60
  text "MATERIAL:" at 11328.46,5047.54 h60
  text "FR-4 High Tg" at 12314.9,4907.21 h60
  text "FR-408" at 11749.46,4898.64 h60
  text "OTHER" at 13237.46,4898.64 h60
  text "X" at 12160,4895 h60
  text "62 MIL (1.6mm) +/-10%" at 12069.56,4735.92 h60
  text "THICKNESS:" at 11403.23,4731.64 h60
  text "X" at 11941.4,4731.64 h60
  text "OTHER" at 13354.46,4731.64 h60
  text "TOLERANCE:" at 11403.23,4573.64 h60
  text "X" at 12242.53,4573.64 h60
  text "ANSI IPC-6012 TYPE 3 CLASS 2" at 12429.48,4573.64 h60
  text "OTHER +/-" at 12429.46,4417.64 h60
  text "BOW & TWIST:" at 11403.23,4260.64 h60
  text "X" at 12242.53,4260.64 h60
  text "ANSI IPC-6012 TYPE 3 CLASS 2" at 12429.48,4260.64 h60
  text "OTHER +/-" at 12429.46,4102.13 h60
  text "DRILLING:" at 11328.46,3963.64 h60
  text "REFERENCE:" at 11403.23,3846.64 h60
  text "X" at 12051.46,3846.64 h60
  text "AS SHOWN" at 12238.46,3846.64 h60
  text "X" at 12952.46,3846.64 h60
  text "NC_DRILL FILES" at 13089.46,3846.64 h60
  text "PTH COPPER THICKNESS:" at 11403.23,3688.64 h60
  text "X" at 12533.46,3688.64 h60
  text "20-30 um" at 12670.46,3688.64 h60
  text "OTHER" at 13387.46,3688.64 h60
  text "BOARD FINISH:" at 11328.46,3529.64 h60
  text "SILKSCREEN:" at 11483.68,3411.64 h60
  text "X" at 12432.46,3411.64 h60
  text "TOP" at 12558.46,3411.64 h60
  text "X" at 12942.46,3411.64 h60
  text "BOTTOM" at 13069.46,3411.64 h60
  text "SILKSCREEN COLOR:" at 11483.68,3244.64 h60
  text "X" at 12431.42,3244.64 h60
  text "WHITE" at 12558.46,3244.64 h60
  text "OTHER" at 13069.46,3244.64 h60
  text "X" at 12562.42,3085.44 h60
  text "GREEN" at 12689.46,3085.44 h60
  text "OTHER" at 13307.46,3085.44 h60
  text "SOLDER RESIST COLOR:" at 11483.68,3074.64 h60
  text "X" at 12562.42,2915.44 h60
  text "MATTE" at 12689.46,2915.44 h60
  text "SEMI-GLOSS" at 13307,2914.8 h60
  text "IMMERSION GOLD (ENIG)" at 12389.46,2726.92 h60
  text "ENEPIG" at 13727,2723.64 h60
  text "SURFACE FINISH:" at 11328.46,2722.64 h60
  text "X" at 12202.51,2722.64 h60
  text "IMM. TIN/SILVER OR EQUIV" at 11658,2565.64 h60
  text "OTHER" at 13089.46,2565.64 h60
  text "ARRAY/PANEL:" at 11328.46,2386.64 h60
  text "CUT AND TRIM PER M1 BOARD OUTLINE" at 12389.46,2382.35 h60
  text "N.C. ROUTE" at 12389.46,2230.64 h60
  text "X" at 13068.46,2230.64 h60
  text "V. SCORE" at 13255.46,2230.64 h60
  text "CERTIFICATION:" at 11328.46,2093.64 h60
  text "MATERIALS AND WORKMANSHIP FOR ALL PCBS" at 12053.46,2093.64 h60
  text "TO MEET OR EXCEED THE REQUIREMENTS OF:" at 12053.46,1995.64 h60
  text "X" at 11679.96,1859.13 h60
  text "ANSI IPC-A-600F CLASS ->" at 11818.96,1859.13 h60
  text "X" at 13458.02,1859.13 h60
  text "2" at 13576.96,1859.14 h60
  text "1" at 13261.96,1857.64 h60
  text "3" at 13930.96,1857.64 h60
  text "X" at 12494.02,1699.64 h60
  text "RoHS" at 12630.96,1699.64 h60
  text "OTHER" at 13275.36,1699.64 h60
  text "PER ORDER" at 13672.42,1699.64 h60
  text "ALL BOARDS MUST MEET OR EXCEED UL94-V0 REQUIREMENTS." at 11356,1534 h60
  text "PCB MUST BEAR THE UL94V-0 UL REGISTERED MATERIAL ID NUMBER" at 11356,1414 h60
  text "ADDITIONAL REQUIREMENTS:" at 11328.46,1240.64 h60
  text "MICROSECTION:" at 11403.23,1125.64 h60
  text "YES" at 12308.96,1125.64 h60
  text "REQUIRED" at 13170.46,969.49 h60
  text "BARE BOARD ELEC. TEST:" at 11403.23,966.64 h60
  text "NONE" at 12708.96,966.64 h60
  text "X" at 13043.46,966.64 h60
  text "PER ORDER" at 13762.46,966.64 h60
  text ".Layer_Name" at 577,-858.49 h60
M11 Gerber Information:
  lines w10: -292,-930.17 6308,-930.17 ; -292,-726.83 6310,-726.83 ; -292,-523.5 -292,-1133.5 3713,-1133.5 6310,-1133.5 6310,-523.5 -291.5,-523.5 -291.5,-1133.5 1284,-1133.5 ; 2173,-1133.5 2173,-523.5 ; 3440,-726.83 3440,-523.5 ; 4280,-726.83 4280,-523.5 ; 4902,-1140 4902,-937.17
  text "ALL ARTWORK VIEWED FROM TOP SIDE" at -228.5,-655.67 h60
  text "BOARD #:" at 2248,-655.67 h60
  text ".PRJ_Number" at 2793.5,-655.67 h60
  text "REV:" at 3638,-655.67 h60
  text ".PCB_Rev" at 3929.5,-655.67 h60
  text "SVN REV:" at 4476,-655.67 h60
  text ".VersionControl_RevNumber" at 4982,-655.67 h60
  text "LAYER NAME =" at -228.5,-858.49 h60
  text "TID #:" at 2248,-859 h60
  text ".TID" at 2793.5,-859 h60
  text "PLOT NAME =" at -228.5,-1064.34 h60
  text ".plot_File_Name" at 577,-1064.34 h60
  text "GENERATED    :" at 2250,-1064.34 h60
  text ".Print_Date" at 3119.5,-1064.34 h60
  text ".Print_Time" at 3848.5,-1064.34 h60
  text "TEXAS INSTRUMENTS" at 5113,-1064.34 h60
M12 Stackup:
  drawing of 191 lines, arcs and shapes, not listed
  text "Layer" at 9790.58,7830 h60
  text "Name" at 10200.49,7830 h60
  text "Material" at 11130.23,7830 h60
  text "Thickness" at 11990,7830 h60
  text "Constant" at 12639.84,7830 h60
  text "Board Layer Stack" at 13209.7,7830 h60
  text "1" at 9790.58,7710 h60
  text "Top Overlay" at 10200.49,7710 h60
  text "2" at 9790.58,7590 h60
  text "Top Solder" at 10200.49,7590 h60
  text "Solder Resist" at 11130.23,7590 h60
  text "0.40mil" at 11990,7590 h60
  text "3.5" at 12639.84,7590 h60
  text "3" at 9790.58,7470 h60
  text "Top Layer" at 10200.49,7470 h60
  text "Copper" at 11130.23,7470 h60
  text "1.40mil" at 11990,7470 h60
  text "4" at 9790.58,7350 h60
  text "Dielectric1" at 10200.49,7350 h60
  text "FR-4" at 11130.23,7350 h60
  text "59.20mil" at 11990,7350 h60
  text "4.8" at 12639.84,7350 h60
  text "5" at 9790.58,7230 h60
  text "Bottom Layer" at 10200.49,7230 h60
  text "Copper" at 11130.23,7230 h60
  text "1.40mil" at 11990,7230 h60
  text "6" at 9790.58,7110 h60
  text "Bottom Solder" at 10200.49,7110 h60
  text "Solder Resist" at 11130.23,7110 h60
  text "0.40mil" at 11990,7110 h60
  text "3.5" at 12639.84,7110 h60
  text "7" at 9790.58,6990 h60
  text "Bottom Overlay" at 10200.49,6990 h60
  text ".Layer_Name" at 577,-858.49 h60
M13 Component Bodies Top:
  text ".Layer_Name" at 577,-858.49 h60
M14 Component Bodies Bottom:
  text ".Layer_Name" at 577,-858.49 h60
M15 Courtyards Top:
  text ".Layer_Name" at 577,-858.49 h60
M16 Courtyards Bottom:
  text ".Layer_Name" at 577,-858.49 h60
Drill Drawing:
  text ".Layer_Name" at 577,-858.49 h60

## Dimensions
0,-400 to 1000,-400 on M2 Board Dimensions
